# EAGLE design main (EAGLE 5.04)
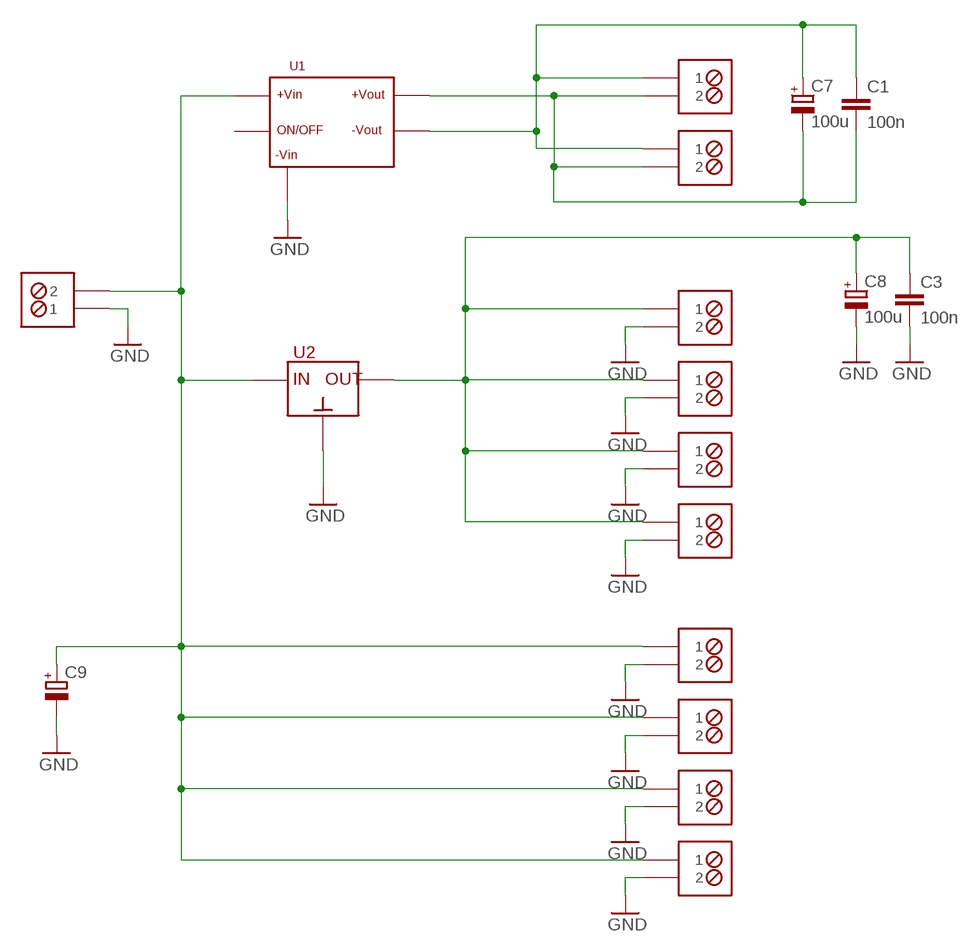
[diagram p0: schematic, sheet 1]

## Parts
C1  100n  C-EUC0603  [C0603]
C3  100n  C-EUC0603  [C0603]
C7  100u  CPOL-EUE2.5-7  [E2,5-7]
C8  100u  CPOL-EUE2.5-7  [E2,5-7]
C9  CPOL-EUE5-13  [E5-13]
CON1  LISTWA_ZACISKOWA5MM_2X1  [LISTWA_ZACISKOWA5MM_2X1]
CON2  LISTWA_ZACISKOWA5MM_2X1  [LISTWA_ZACISKOWA5MM_2X1]
CON3  LISTWA_ZACISKOWA5MM_2X1  [LISTWA_ZACISKOWA5MM_2X1]
CON4  LISTWA_ZACISKOWA5MM_2X1  [LISTWA_ZACISKOWA5MM_2X1]
CON5  LISTWA_ZACISKOWA5MM_2X1  [LISTWA_ZACISKOWA5MM_2X1]
CON6  LISTWA_ZACISKOWA5MM_2X1  [LISTWA_ZACISKOWA5MM_2X1]
CON7  LISTWA_ZACISKOWA5MM_2X1  [LISTWA_ZACISKOWA5MM_2X1]
CON8  LISTWA_ZACISKOWA5MM_2X1  [LISTWA_ZACISKOWA5MM_2X1]
CON9  LISTWA_ZACISKOWA5MM_2X1  [LISTWA_ZACISKOWA5MM_2X1]
CON10  LISTWA_ZACISKOWA5MM_2X1  [LISTWA_ZACISKOWA5MM_2X1]
CON11  LISTWA_ZACISKOWA5MM_2X1  [LISTWA_ZACISKOWA5MM_2X1]
U1  TMR2411  [STABIZO34]
U2  TSR1-2450  [STAB3IN]

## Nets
GND: C3.2 C8.- C9.- CON1.P$1 CON2.P$2 CON3.P$2 CON4.P$2 CON5.P$2 CON6.P$2 CON7.P$2 CON8.P$2 CON9.P$2 U1.1(-VIN) U2.2(GND)
N$1: C9.+ CON1.P$2 CON2.P$1 CON3.P$1 CON4.P$1 CON5.P$1 U1.2(+VIN) U2.1(IN)
N$3: C1.1 C7.+ CON10.P$1 CON11.P$1 U1.6(-VOUT)
N$4: C1.2 C7.- CON10.P$2 CON11.P$2 U1.5(+VOUT)
N$5: C3.1 C8.+ CON6.P$1 CON7.P$1 CON8.P$1 CON9.P$1 U2.3(OUT)
Unconnected: U1.3(ON/OFF)

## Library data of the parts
C1 C3 = rcl:C-EU: CAPACITOR, European symbol
C7-C9 = rcl:CPOL-EU: POLARIZED CAPACITOR, European symbol
CON1-CON11 = konektory:LISTWA_ZACISKOWA5MM_2X1
U1 = stabilizatory_imp:TMR2411: Stabilizator impusowy - izolowany 18-36 na 5V 400mA
U2 = stabilizatory_imp:TSR1-2450: stabilizator impusowy - 6.5-35V in, 5V out, 1A

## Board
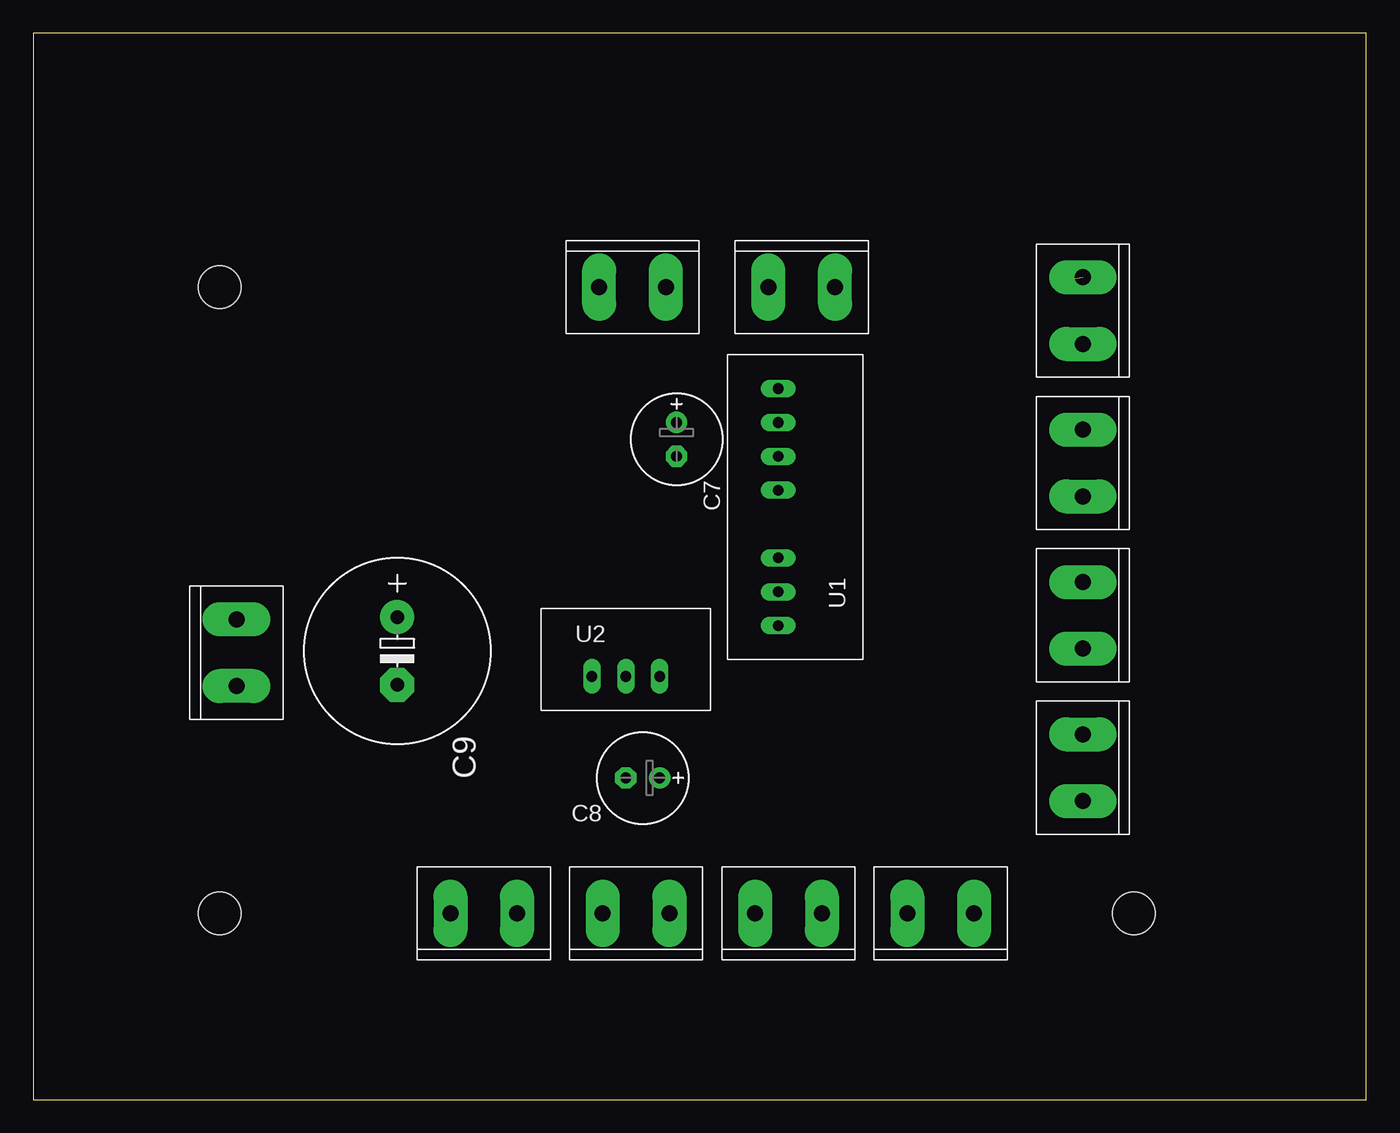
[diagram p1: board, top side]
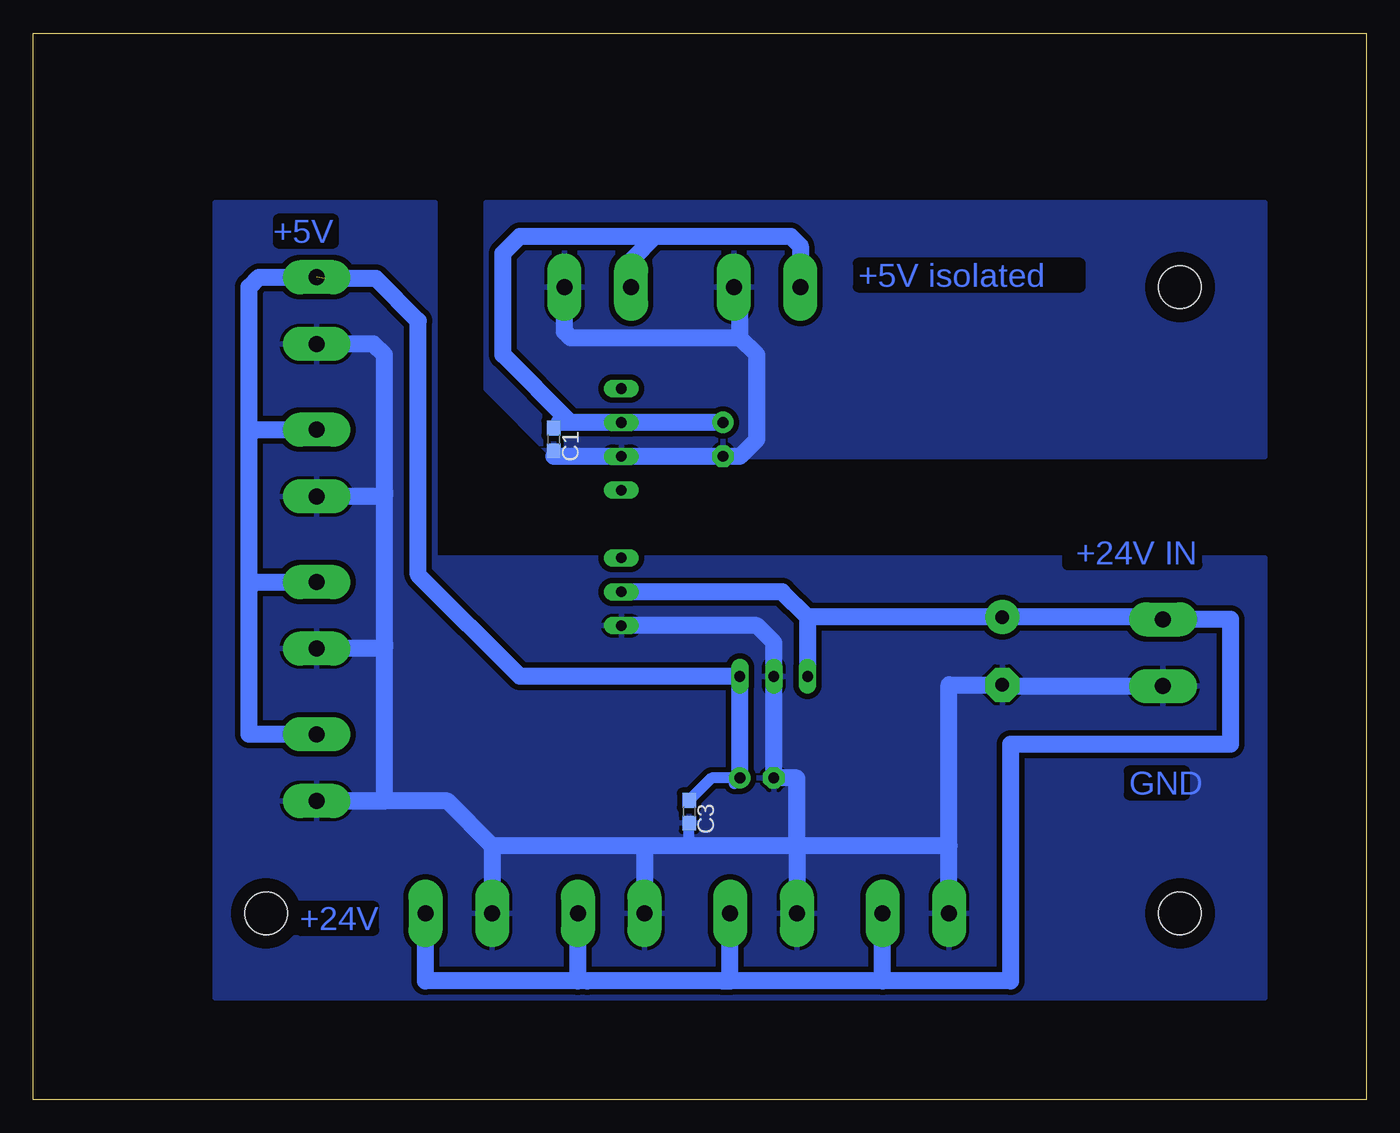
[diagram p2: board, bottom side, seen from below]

Size 100 x 80 mm. Coordinates in mm from the lower left corner, seen from the top.
Outline: 0,0 100,0 100,80 0,80 0,0
Copper layers (1*16): Top 0.035mm / dielectric 1.5mm / Bottom 0.035mm
Design rules "default": minimum track width 10mil, minimum drill 24mil, track to track 8mil, track to pad 8mil, pad to pad 8mil, via to via 8mil, smd to smd 8mil, copper to edge 40mil, drill to drill 8mil, minimum pad ring 10mil, minimum via ring 8mil, stop-mask expansion 4mil, vias tented up to drill 0mil, thermal gap 10mil
Holes 3.2 mm at 13.97,60.96 13.97,13.97 82.55,13.97

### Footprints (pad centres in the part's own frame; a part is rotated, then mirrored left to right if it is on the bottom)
C0603 = smd 1.1 x 1: 1 -0.85,0; 2 0.85,0
E2,5-7 = drill 0.813 pad 1.6 round: + -1.27,0 | drill 0.813 pad 1.6 octagon: - 1.27,0
E5-13 = drill 1.016 pad 2.54 round: + -2.54,0 | drill 1.016 pad 2.54 octagon: - 2.54,0
LISTWA_ZACISKOWA5MM_2X1 = drill 1.2 pad 2.54 long: P$1 -2,0; P$2 3,0
STABIZO34 = drill 0.8 long: 1 -7.62,0; 2 -5.08,0; 3 -2.54,0; 4 2.54,0; 5 5.08,0; 6 7.62,0; 7 10.16,0
STAB3IN = drill 0.8 long: 1 -2.54,0; 2 0,0; 3 2.54,0

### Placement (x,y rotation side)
C1  60.96,49.53 270 bottom
C3  50.8,21.59 270 bottom
C7  48.26,49.53 270 top
C8  45.72,24.13 180 top
C9  27.3,33.66 270 top
CON1  15.24,33.02 90 top
CON2  57.15,13.97 180 top
CON3  34.29,13.97 180 top
CON4  68.58,13.97 180 top
CON5  45.72,13.97 180 top
CON6  78.74,25.4 270 top
CON7  78.74,59.69 270 top
CON8  78.74,48.26 270 top
CON9  78.74,36.83 270 top
CON10  44.45,60.96 0 top
CON11  57.15,60.96 0 top
U1  55.88,43.18 90 top
U2  44.45,31.75 0 top

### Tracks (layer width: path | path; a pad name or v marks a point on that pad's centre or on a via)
GND
  Bottom 0.813: 50.8,19.05 C3.2
  Bottom 1.27: 42.72,19.05 CON5.P$2 | 42.72,19.05 42.72,24.13 C8.- U2.2 44.45,34.29 45.72,35.56 U1.1 | CON3.P$2 31.29,19.05 | 31.29,19.05 42.72,19.05 | 65.58,19.05 CON4.P$2 | 42.72,19.05 50.8,19.05 54.61,19.05 | 54.61,19.05 65.58,19.05 | CON2.P$2 54.15,19.05 54.61,19.05 | 31.29,19.05 31.29,31.11 C9.- 27.3,31.02 CON1.P$1 | 65.58,19.05 68.93,22.4 CON6.P$2 73.66,22.4 73.66,34.29 | 73.66,34.29 73.66,45.72 | 73.66,45.72 73.66,55.88 74.47,56.69 CON7.P$2 | CON8.P$2 73.66,45.26 73.66,45.72 | CON9.P$2 73.66,33.83 73.66,34.29
  pour Bottom (isolate 0.406): 7.62,40.64 69.85,40.64 69.85,67.31 86.36,67.31 86.36,7.62 7.62,7.62
N$1
  Bottom 1.27: CON4.P$1 70.58,8.89 58.42,8.89 | 36.29,8.89 48.26,8.89 | 48.26,8.89 58.42,8.89 | CON5.P$1 47.72,8.89 48.26,8.89 | CON2.P$1 59.15,8.89 58.42,8.89 | 26.67,36.2 15.24,36.2 CON1.P$2 10.16,36.02 10.16,26.67 26.67,26.67 26.67,8.89 36.29,8.89 | 26.67,36.2 C9.+ | 41.91,36.2 U2.1 | 26.67,36.2 41.91,36.2 | 36.29,8.89 CON3.P$1 | U1.2 43.81,38.1 41.91,36.2
N$3
  Bottom 0.813: 60.54,50.8 C1.1
  Bottom 1.27: C7.+ U1.6 59.69,50.8 | CON10.P$1 42.45,64.04 43.18,64.77 53.34,64.77 | 53.34,64.77 55.15,62.96 CON11.P$1 | 59.69,50.8 64.77,55.88 64.77,63.5 63.5,64.77 53.34,64.77 | 59.69,50.8 60.54,50.8
N$4
  Bottom 0.813: 60.96,48.26 C1.2
  Bottom 1.27: 46.99,57.15 45.72,55.88 45.72,49.53 46.99,48.26 C7.- U1.5 60.96,48.26 | 46.99,57.15 46.99,60.5 CON10.P$2 | CON11.P$2 60.15,57.61 59.69,57.15 46.99,57.15
  pour Bottom (isolate 0.406): 7.62,48.26 60.96,48.26 66.04,53.34 66.04,67.31 10.16,67.31 7.62,67.31
N$5  (1 unrouted)
  Bottom 0.813: 47.41,23.71 C8.+ 49.11,24.13 C3.1
  Bottom 1.27: 78.11,61.59 74.3,61.59 71.12,58.42 71.12,39.37 63.5,31.75 U2.3 C8.+ | CON6.P$1 83.82,27.4 83.82,38.1 | 83.82,38.1 83.82,49.53 | 83.82,49.53 83.82,60.96 83.09,61.69 CON7.P$1 | CON8.P$1 83.09,50.26 arc-90 83.82,49.53 | CON9.P$1 83.09,38.83 arc-90 83.82,38.1

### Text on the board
Bottom: +5V | +5V isolated | +24V IN | GND | +24V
